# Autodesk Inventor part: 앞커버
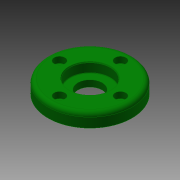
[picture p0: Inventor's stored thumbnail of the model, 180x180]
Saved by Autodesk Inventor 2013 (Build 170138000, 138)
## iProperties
Created: 2015-09
Part Number: 앞커버
Material: 알루미늄 6061
Document SubType Name: Modeling
Designer: mduedu
Density: 1 g/cm^3
Author: mduedu
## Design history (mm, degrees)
sketch "스케치1"
  geometry: L1 (0, 7.5)-(0, -7.5); L2 (0, 7.5)-(31, 7.5); L3 (31, 7.5)-(31, -2.5); L4 (31, -2.5)-(17.5, -2.5); L5 (17.5, -2.5)-(17.5, -7.5); L6 (17.5, -7.5)-(0, -7.5); 2 further points
  constraints: 12 end point, 2 parallel, 2 perpendicular, 1 coincident, 1 horizontal, 1 midpoint, 1 vertical
  dimensions: "d0" = 15 distance of L1.start L1.end; "d1" = 62 diameter of L3 L1; "d2" = 35 diameter of L5 L1; "d3" = 10 distance of L2.end L3.end
revolve "회전1" sketch "스케치1" stored, may be unused: angle "d4" = 90 deg
hole "구멍1" diameter "d7" = 30; stored, may be unused: countersink angle "d11" = 90 deg, drill point angle "d13" = 0 deg; dims "d5" = 10, "d6" = 10, "d8" = 6, "d9" = 4, "d10" = 2, "d12" = 7.3
hole "구멍2" diameter "d16" = 18; stored, may be unused: countersink angle "d20" = 90 deg, drill point angle "d22" = 0 deg; dims "d14" = 10, "d15" = 10, "d17" = 6, "d18" = 4, "d19" = 2, "d21" = 7.3
chamfer "모따기2" distance "d26" = 0.7; stored, may be unused: second distance "d27" = 2, angle "d28" = 30 deg
fillet "모깎기1" dims "d29" = 0.3
sketch "스케치3"
  geometry: C1 r 15.404 at (0, 0) reference; A1 r 24 centre (0, 0) between (0, 24) and (0, -24); 2 further points
  constraints: 4 point on circle, 2 horizontal alignment, 2 vertical alignment, 1 centre point, 1 coincident
  dimensions: "d60" = 48 diameter of A1
hole "구멍3" sketch "스케치3" at (0, 24), (-24, 0), (24, 0), (0, -24) diameter "d36" = 4.5; stored, may be unused: countersink angle "d40" = 90 deg, drill point angle "d42" = 0 deg; dims "d37" = 6, "d38" = 8, "d39" = 4.6, "d41" = 8
chamfer "모따기3" distance "d43" = 1; stored, may be unused: second distance "d44" = 2, angle "d45" = 45 deg
fillet "모깎기2" dims "d46" = 3
hole "구멍4" diameter "d49" = 30; stored, may be unused: countersink angle "d53" = 90 deg, drill point angle "d55" = 0 deg; dims "d50" = 6, "d51" = 4, "d52" = 2, "d54" = 3, "d56" = 10, "d57" = 10
fillet "모깎기3" dims "d58" = 3
node "솔리드1"
sketch "스케치2" dims "d30" = 48
  geometry: 6 further points
  constraints: 2 vertical alignment, 1 coincident, 7 other
  dimensions: "d34" = 360 deg dimension on point (0, 0) point (0, 24) (derived)
